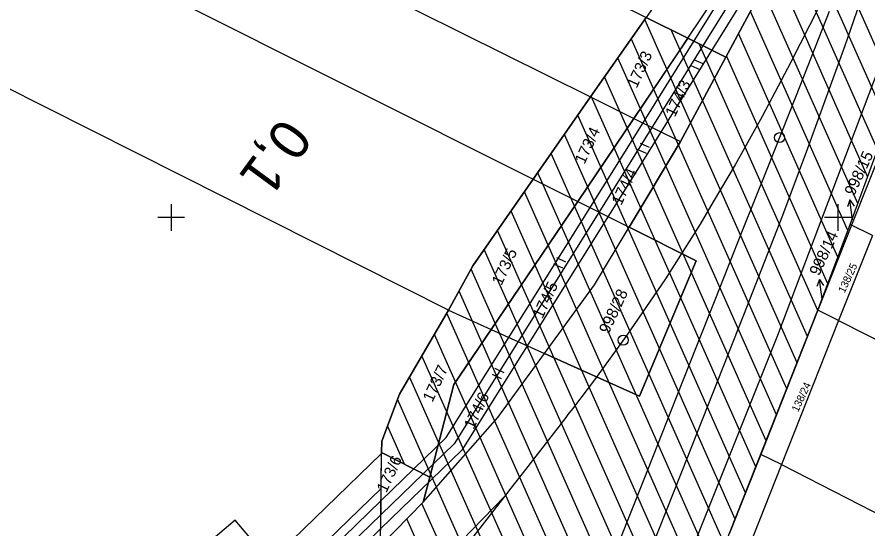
# Model space of a CAD drawing. Extents: x -755061 to -754557, y -1162352 to -1161657.
# Drawn here: x -754923.1 to -754795.5, y -1162146.7 to -1162070 of the extents above; entities that cross this region are included whole.
import ezdxf

# ---------------------------------------------------------------- set-up
doc = ezdxf.new("R2010")
doc.units = 0
for name, color, linetype in [('ADJ_Síť', 7, 'Continuous'), ('DTA-TZ', 7, 'Continuous'), ('DTA_DZ_DO_hranice', 7, 'Continuous'), ('DTA_DZ_DO_ostatní', 7, 'Continuous'), ('DTA_DZ_DO_ZPF', 7, 'Continuous'), ('DTA_ochranné pásmo', 7, 'Continuous'), ('DTA_projektovaný_stav', 7, 'Continuous'), ('DTA_správa_investora', 7, 'Continuous'), ('DTA_TZ_ZPF', 7, 'Continuous'), ('KN_Katastrální hranice', 7, 'Continuous'), ('KN_Vrstva 55', 7, 'Continuous'), ('KN_Vrstva 57', 7, 'Continuous'), ('KN_Vrstva 58', 7, 'Continuous'), ('Staniceni a namezniky', 7, 'Continuous'), ('Vrstva 1', 7, 'Continuous'), ('Vrstva 53', 7, 'Continuous')]:
    doc.layers.add(name, color=color, linetype=linetype)

msp = doc.modelspace()

# ---------------------------------------------------------------- linework, layer by layer
at = {"layer": 'ADJ_Síť'}
for points in [[(-754900, -1162098), (-754900, -1162100), (-754900, -1162102)], [(-754900, -1162098), (-754900, -1162100), (-754900, -1162102)], [(-754800, -1162098), (-754800, -1162100), (-754800, -1162102)], [(-754800, -1162098), (-754800, -1162100), (-754800, -1162102)], [(-754898, -1162100), (-754900, -1162100), (-754902, -1162100)], [(-754898, -1162100), (-754900, -1162100), (-754902, -1162100)], [(-754798, -1162100), (-754800, -1162100), (-754802, -1162100)], [(-754798, -1162100), (-754800, -1162100), (-754802, -1162100)]]:
    msp.add_lwpolyline(points, dxfattribs=at)
at = {"layer": 'DTA-TZ'}
msp.add_lwpolyline([(-754815.64, -1162062.89), (-754809.29, -1162051.78), (-754815.21, -1162048.8), (-754824.54, -1162063.98), (-754828.75, -1162070.02), (-754822.47, -1162073.13)], close=True, dxfattribs=at)
msp.add_lwpolyline([(-754923.5, -1162192.2), (-754927.24, -1162190.37), (-754917.66, -1162184.92), (-754903.67, -1162174.98), (-754894.6, -1162165.92), (-754868.47, -1162140.62), (-754868.42, -1162135.23), (-754861.18, -1162138.93), (-754862.16, -1162142.69), (-754868.56, -1162149.23), (-754896.07, -1162173.88), (-754915.78, -1162187.87), (-754923.5, -1162192.2)], dxfattribs=at)
at = {"layer": 'DTA_DZ_DO_hranice'}
for points in [[(-754816.76, -1162075.96), (-754812.88, -1162068.75), (-754805.89, -1162053.43), (-754794.46, -1162027.05), (-754775.38, -1161978.82), (-754774.5, -1161950.49), (-754763.88, -1161940.21)], [(-754785.9, -1161947.61), (-754784.8, -1161953.94), (-754785.77, -1161974.89), (-754795.69, -1162003.82), (-754808.6, -1162035.49), (-754813.58, -1162046.15), (-754815.21, -1162048.8), (-754824.54, -1162063.98), (-754828.75, -1162070.02), (-754837.06, -1162081.94), (-754845.66, -1162094.27), (-754854.71, -1162107.25), (-754858.37, -1162113.93), (-754865.75, -1162126.5), (-754868.4, -1162133.56), (-754868.42, -1162135.23)], [(-754882.86, -1162162.04), (-754868.56, -1162149.23), (-754862.16, -1162142.69), (-754850.97, -1162130.01), (-754843.96, -1162120.41), (-754829.74, -1162126.8), (-754821.22, -1162106.53), (-754831.28, -1162101.48), (-754823.58, -1162088.63), (-754816.76, -1162075.96)], [(-754868.42, -1162135.23), (-754868.42, -1162135.42), (-754885.14, -1162151.61), (-754890.41, -1162145.41), (-754900.32, -1162153.82), (-754894.5, -1162160.68), (-754900.94, -1162166.91), (-754920.36, -1162180.69), (-754945.08, -1162194.78)]]:
    msp.add_lwpolyline(points, dxfattribs=at)
at = {"layer": 'DTA_DZ_DO_ostatní'}
msp.add_lwpolyline([(-754822.47, -1162073.13), (-754830.58, -1162085.16), (-754839, -1162097.61), (-754851.98, -1162116.8), (-754857.56, -1162125.05), (-754861.18, -1162138.93), (-754868.42, -1162135.23), (-754868.4, -1162133.56), (-754865.75, -1162126.5), (-754858.37, -1162113.93), (-754854.71, -1162107.25), (-754845.66, -1162094.27), (-754837.06, -1162081.94), (-754828.75, -1162070.02), (-754822.47, -1162073.13)], dxfattribs=at)
msp.add_lwpolyline([(-754843.96, -1162120.41), (-754836.46, -1162110.13), (-754831.28, -1162101.48), (-754821.22, -1162106.53), (-754829.74, -1162126.8)], close=True, dxfattribs=at)
at = {"layer": 'DTA_DZ_DO_ZPF'}
msp.add_lwpolyline([(-754822.47, -1162073.13), (-754830.58, -1162085.16), (-754839, -1162097.61), (-754851.98, -1162116.8), (-754857.56, -1162125.05), (-754861.18, -1162138.93), (-754862.16, -1162142.69), (-754850.97, -1162130.01), (-754843.96, -1162120.41), (-754836.46, -1162110.13), (-754831.28, -1162101.48), (-754823.58, -1162088.63), (-754816.76, -1162075.96)], close=True, dxfattribs=at)
msp.add_lwpolyline([(-754927.24, -1162190.37), (-754917.66, -1162184.92), (-754903.67, -1162174.98), (-754894.6, -1162165.92), (-754868.47, -1162140.62), (-754868.42, -1162135.42), (-754885.14, -1162151.61), (-754890.41, -1162145.41), (-754900.32, -1162153.82), (-754894.5, -1162160.68), (-754900.94, -1162166.91), (-754920.36, -1162180.69), (-754932.68, -1162187.72)], dxfattribs=at)
at = {"layer": 'DTA_ochranné pásmo'}
for p, q in [((-754832.34, -1162090.86), (-754811.2, -1162056.88)), ((-754808.54, -1162058.27), (-754829.8, -1162092.44)), ((-754858.72, -1162132.98), (-754832.34, -1162090.86)), ((-754829.8, -1162092.44), (-754856.37, -1162134.88)), ((-754868.49, -1162142.45), (-754858.72, -1162132.98)), ((-754856.37, -1162134.88), (-754868.53, -1162146.66)), ((-754868.49, -1162142.45), (-754897.74, -1162170.77)), ((-754868.53, -1162146.66), (-754868.49, -1162142.45)), ((-754895.81, -1162173.08), (-754868.53, -1162146.66))]:
    msp.add_line(p, q, dxfattribs=at)
at = {"layer": 'DTA_projektovaný_stav'}
msp.add_lwpolyline([(-754758.34, -1161933.06), (-754762.34, -1161937.68), (-754763.29, -1161936.85), (-754776.47, -1161949.62), (-754777.37, -1161978.41), (-754796.3, -1162026.28), (-754809.87, -1162057.58), (-754831.07, -1162091.65), (-754857.54, -1162133.93), (-754885.68, -1162161.18), (-754896.77, -1162171.93), (-754916.86, -1162186.18), (-754942.05, -1162200.54), (-754965.03, -1162211.64), (-754990.89, -1162220.78), (-755014.11, -1162227.27), (-755008.76, -1162253.14), (-755005.05, -1162256.17)], dxfattribs=at)
at = {"layer": 'DTA_správa_investora'}
for p, q in [((-754791.04, -1162081.76), (-754810.13, -1162038.77)), ((-754792.53, -1162085.79), (-754806.69, -1162053.92)), ((-754794.02, -1162089.83), (-754808.28, -1162057.73)), ((-754795.51, -1162093.87), (-754809.87, -1162061.54)), ((-754796.99, -1162097.92), (-754811.46, -1162065.35)), ((-754798.48, -1162101.96), (-754813.07, -1162069.11)), ((-754806.09, -1162121.79), (-754828.95, -1162070.31)), ((-754804.54, -1162117.88), (-754824.97, -1162071.89)), ((-754807.63, -1162125.69), (-754830.96, -1162073.19)), ((-754799.98, -1162105.96), (-754814.87, -1162072.45)), ((-754802.99, -1162113.98), (-754820.76, -1162073.98)), ((-754809.18, -1162129.6), (-754832.96, -1162076.06)), ((-754801.49, -1162109.97), (-754816.67, -1162075.79)), ((-754810.73, -1162133.5), (-754834.97, -1162078.94)), ((-754812.28, -1162137.41), (-754836.97, -1162081.82)), ((-754813.83, -1162141.31), (-754838.98, -1162084.69)), ((-754815.37, -1162145.22), (-754840.98, -1162087.57)), ((-754816.94, -1162149.08), (-754842.99, -1162090.44)), ((-754818.53, -1162152.9), (-754844.99, -1162093.32)), ((-754820.12, -1162156.71), (-754847, -1162096.19)), ((-754821.71, -1162160.53), (-754849, -1162099.07)), ((-754823.29, -1162164.34), (-754851.01, -1162101.94)), ((-754824.88, -1162168.15), (-754853.02, -1162104.82)), ((-754826.47, -1162171.97), (-754854.99, -1162107.76)), ((-754828.06, -1162175.78), (-754856.8, -1162111.07)), ((-754829.65, -1162179.6), (-754858.62, -1162114.36)), ((-754831.24, -1162183.41), (-754860.49, -1162117.55)), ((-754832.82, -1162187.23), (-754862.36, -1162120.73)), ((-754834.41, -1162191.04), (-754864.23, -1162123.91)), ((-754836, -1162194.86), (-754866.03, -1162127.25)), ((-754864.99, -1162136.98), (-754867.53, -1162131.25)), ((-754837.59, -1162198.67), (-754862.36, -1162142.9)), ((-754839.18, -1162202.48), (-754864.62, -1162145.2))]:
    msp.add_line(p, q, dxfattribs=at)
for points in [[(-755057.07, -1162235.3), (-755060.75, -1162244.84), (-754884.82, -1162312.55), (-754851.45, -1162231.96), (-754816.22, -1162147.35), (-754802.96, -1162113.9), (-754798.15, -1162101.07), (-754793.13, -1162087.4), (-754789, -1162076.26), (-754760.29, -1162004.33), (-754756.33, -1161996.85), (-754754.27, -1161988.55), (-754747.84, -1161978.77), (-754745.89, -1161978.47), (-754750.32, -1161972.64), (-754749.74, -1161970.12), (-754747.41, -1161959.83), (-754731.42, -1161979.09), (-754717.5, -1161955.11), (-754704.12, -1161932.06), (-754747.69, -1161915.3)], [(-754812.88, -1162068.75), (-754816.76, -1162075.96), (-754822.47, -1162073.13), (-754828.75, -1162070.02), (-754837.06, -1162081.94), (-754854.71, -1162107.25), (-754858.37, -1162113.93), (-754865.75, -1162126.5), (-754868.4, -1162133.56), (-754868.42, -1162135.23), (-754861.18, -1162138.93), (-754862.16, -1162142.69), (-754868.56, -1162149.23), (-754896.07, -1162173.88), (-754900.06, -1162176.77), (-754915.78, -1162187.87), (-754923.5, -1162192.2)]]:
    msp.add_lwpolyline(points, dxfattribs=at)
at = {"layer": 'DTA_TZ_ZPF'}
msp.add_lwpolyline([(-754822.47, -1162073.13), (-754815.64, -1162062.89), (-754810.12, -1162053.37), (-754809.29, -1162051.78), (-754806.4, -1162053.23), (-754812.88, -1162068.75), (-754816.76, -1162075.96)], close=True, dxfattribs=at)
at = {"layer": 'KN_Katastrální hranice'}
for p, q in [((-754792.54, -1162087.63), (-754797.91, -1162101.16)), ((-754797.91, -1162101.16), (-754802.96, -1162113.9)), ((-754802.96, -1162113.9), (-754811.54, -1162135.54)), ((-754811.54, -1162135.54), (-754816.22, -1162147.35))]:
    msp.add_line(p, q, dxfattribs=at)
at = {"layer": 'KN_Vrstva 55'}
for p, q in [((-754828.75, -1162070.02), (-754837.06, -1162081.94)), ((-754828.75, -1162070.02), (-754822.47, -1162073.13)), ((-754822.47, -1162073.13), (-754816.76, -1162075.96)), ((-754816.76, -1162075.96), (-754823.58, -1162088.63)), ((-754837.06, -1162081.94), (-754845.66, -1162094.27)), ((-754837.06, -1162081.94), (-754830.58, -1162085.16)), ((-754839, -1162097.61), (-754830.58, -1162085.16)), ((-754830.58, -1162085.16), (-754823.58, -1162088.63)), ((-754798.15, -1162101.07), (-754793.13, -1162087.4)), ((-754792.54, -1162087.63), (-754797.91, -1162101.16)), ((-754792.54, -1162087.63), (-754797.91, -1162101.16)), ((-754823.58, -1162088.63), (-754831.28, -1162101.48)), ((-754845.66, -1162094.27), (-754839, -1162097.61)), ((-754851.98, -1162116.8), (-754839, -1162097.61)), ((-754839, -1162097.61), (-754831.28, -1162101.48)), ((-754802.96, -1162113.9), (-754798.15, -1162101.07)), ((-754797.91, -1162101.16), (-754802.96, -1162113.9)), ((-754797.91, -1162101.16), (-754802.96, -1162113.9)), ((-754797.91, -1162101.16), (-754798.15, -1162101.07)), ((-754794.8, -1162102.72), (-754797.91, -1162101.16)), ((-754794.8, -1162102.72), (-754799.86, -1162115.47)), ((-754802.96, -1162113.9), (-754811.54, -1162135.54)), ((-754802.96, -1162113.9), (-754811.54, -1162135.54)), ((-754799.86, -1162115.47), (-754802.96, -1162113.9)), ((-754799.86, -1162115.47), (-754808.43, -1162137.05)), ((-754851.98, -1162116.8), (-754843.96, -1162120.41)), ((-754868.56, -1162149.23), (-754868.42, -1162135.23)), ((-754861.18, -1162138.93), (-754868.42, -1162135.23)), ((-754811.54, -1162135.54), (-754816.22, -1162147.35)), ((-754811.54, -1162135.54), (-754816.22, -1162147.35)), ((-754808.43, -1162137.05), (-754811.54, -1162135.54)), ((-754808.43, -1162137.05), (-754817.91, -1162160.94)), ((-754862.16, -1162142.69), (-754861.18, -1162138.93)), ((-754868.56, -1162149.23), (-754862.16, -1162142.69))]:
    msp.add_line(p, q, dxfattribs=at)
for points in [[(-754888.68, -1162311.07), (-754870.17, -1162267.96), (-754836.4, -1162183.6), (-754824.89, -1162157.4), (-754808.97, -1162117.64), (-754790.52, -1162068.93), (-754761.32, -1161999.17), (-754754.27, -1161988.55)], [(-754966.42, -1161999.75), (-754920.4, -1162024.65), (-754828.75, -1162070.02)], [(-754971.75, -1162013.61), (-754934.11, -1162033.82), (-754837.06, -1162081.94)], [(-754977.09, -1162027.47), (-754900.68, -1162066.68), (-754845.66, -1162094.27)], [(-754815.21, -1162048.8), (-754824.54, -1162063.98), (-754828.75, -1162070.02)], [(-754858.37, -1162113.93), (-754985.69, -1162049.81)], [(-754822.47, -1162073.13), (-754815.64, -1162062.89), (-754810.12, -1162053.37), (-754809.29, -1162051.78)], [(-754806.4, -1162053.23), (-754812.88, -1162068.75), (-754816.76, -1162075.96)], [(-754830.58, -1162085.16), (-754823.72, -1162075.01), (-754822.47, -1162073.13)], [(-754845.66, -1162094.27), (-754854.71, -1162107.25), (-754858.37, -1162113.93)], [(-754843.96, -1162120.41), (-754836.46, -1162110.13), (-754831.28, -1162101.48)], [(-754831.28, -1162101.48), (-754821.22, -1162106.53), (-754829.74, -1162126.8), (-754843.96, -1162120.41)], [(-754868.42, -1162135.23), (-754868.4, -1162133.56), (-754865.75, -1162126.5), (-754858.37, -1162113.93)], [(-754865.75, -1162126.5), (-754858.37, -1162113.93), (-754851.98, -1162116.8)], [(-754799.86, -1162115.47), (-754745.23, -1162143.07), (-754710.27, -1162161.07)], [(-754861.18, -1162138.93), (-754857.56, -1162125.05), (-754851.98, -1162116.8)], [(-754862.16, -1162142.69), (-754850.97, -1162130.01), (-754843.96, -1162120.41)], [(-754808.43, -1162137.05), (-754718.71, -1162183.01)]]:
    msp.add_lwpolyline(points, dxfattribs=at)
at = {"layer": 'KN_Vrstva 57'}
for p, q in [((-754798.16, -1162097.38), (-754798.52, -1162098.44)), ((-754797.77, -1162100.36), (-754798.16, -1162097.38)), ((-754798.16, -1162097.38), (-754797.53, -1162098.31)), ((-754802.74, -1162109.29), (-754803.11, -1162110.34)), ((-754802.35, -1162112.26), (-754802.74, -1162109.29)), ((-754802.74, -1162109.29), (-754802.11, -1162110.22))]:
    msp.add_line(p, q, dxfattribs=at)
at = {"layer": 'KN_Vrstva 58'}
for p, q in [((-754820.63, -1162077.9), (-754821.99, -1162077.27)), ((-754820.2, -1162077), (-754821.56, -1162076.36)), ((-754828.24, -1162089.53), (-754829.6, -1162088.9)), ((-754828.66, -1162090.44), (-754830.02, -1162089.8)), ((-754840.78, -1162106.72), (-754842.14, -1162106.08)), ((-754841.21, -1162107.62), (-754842.57, -1162106.99)), ((-754850.01, -1162123.29), (-754851.37, -1162122.66)), ((-754850.43, -1162124.2), (-754851.79, -1162123.57))]:
    msp.add_line(p, q, dxfattribs=at)
at = {"layer": 'Staniceni a namezniky'}
for centre in [(-754808.73, -1162088.04), (-754832.17, -1162118.4)]:
    msp.add_circle(centre, 0.75, dxfattribs=at)
at = {"layer": 'Vrstva 1'}
for points in [[(-754814.09, -1162114.62), (-754808.25, -1162099.68), (-754804.47, -1162089.62), (-754798.9, -1162074.23), (-754793.63, -1162059.03), (-754788.99, -1162045.27)], [(-754802.82, -1162068.46), (-754807.01, -1162076.73), (-754811.35, -1162084.87), (-754815.39, -1162092.12), (-754818.66, -1162097.67), (-754820.65, -1162100.99), (-754825.85, -1162109.19), (-754831.64, -1162117.68), (-754836.49, -1162124.37), (-754839.8, -1162128.71), (-754840.46, -1162129.57), (-754840.79, -1162129.99), (-754847.19, -1162138.25), (-754849.01, -1162140.58), (-754849.98, -1162141.84), (-754854.92, -1162148.19), (-754860.18, -1162155.01)], [(-754855.13, -1162205.06), (-754851.41, -1162195.67), (-754847.87, -1162186.72), (-754844.23, -1162177.57), (-754840.47, -1162168.07), (-754836.48, -1162158.01), (-754832.72, -1162148.55), (-754829.03, -1162139.24), (-754824.91, -1162128.83), (-754821.22, -1162119.52), (-754818.37, -1162112.34), (-754814.26, -1162101.97), (-754810.6, -1162092.76), (-754806.3, -1162081.9), (-754802.77, -1162073.01), (-754801.21, -1162069.06)], [(-754832.58, -1162161.33), (-754823.38, -1162138.13), (-754814.09, -1162114.62)], [(-754839.8, -1162128.71), (-754840.46, -1162129.57), (-754840.79, -1162129.99), (-754847.19, -1162138.25), (-754849.01, -1162140.58), (-754849.98, -1162141.84), (-754861.22, -1162153.45), (-754861.54, -1162153.77), (-754867.4, -1162159.65), (-754873.88, -1162165.79), (-754880.89, -1162172.03), (-754888.58, -1162178.44), (-754889.11, -1162178.86), (-754895.68, -1162183.99), (-754902.86, -1162189.27), (-754906.67, -1162191.94), (-754914.99, -1162197.47), (-754922.58, -1162202.18), (-754930.39, -1162206.7)]]:
    msp.add_lwpolyline(points, dxfattribs=at)
at = {"layer": 'Vrstva 53'}
for points in [[(-754884.82, -1162312.55), (-754851.45, -1162231.96), (-754816.22, -1162147.35), (-754802.96, -1162113.9), (-754798.15, -1162101.07), (-754793.13, -1162087.4), (-754789, -1162076.26), (-754760.29, -1162004.33), (-754756.33, -1161996.85), (-754754.27, -1161988.55), (-754747.84, -1161978.77), (-754745.89, -1161978.47), (-754750.32, -1161972.64), (-754749.74, -1161970.12), (-754747.41, -1161959.83), (-754731.42, -1161979.09), (-754717.5, -1161955.11), (-754704.12, -1161932.06)], [(-754812.88, -1162068.75), (-754816.76, -1162075.96), (-754822.47, -1162073.13), (-754828.75, -1162070.02), (-754837.06, -1162081.94), (-754854.71, -1162107.25), (-754858.37, -1162113.93), (-754865.75, -1162126.5), (-754868.4, -1162133.56), (-754868.42, -1162135.23), (-754861.18, -1162138.93), (-754862.16, -1162142.69), (-754868.56, -1162149.23), (-754896.07, -1162173.88), (-754900.06, -1162176.77), (-754915.78, -1162187.87), (-754923.5, -1162192.2)]]:
    msp.add_lwpolyline(points, dxfattribs=at)

# ---------------------------------------------------------------- texts
at = {"layer": 'KN_Vrstva 57'}
for s, height, p in [('173/3', 1.7, (-754830.16, -1162080.73)), ('174/3', 1.7, (-754824.42, -1162085.06)), ('173/4', 1.7, (-754837.99, -1162092.13)), ('998/15', 1.7, (-754797.54, -1162096.87)), ('174/4', 1.7, (-754832.47, -1162098.3)), ('998/14', 1.7, (-754802.81, -1162108.87)), ('173/5', 1.7, (-754850.44, -1162110.31)), ('138/25', 1.139, (-754798.97, -1162111.43)), ('174/5', 1.7, (-754844.3, -1162115.3)), ('998/28', 1.7, (-754834.36, -1162117.56)), ('173/7', 1.7, (-754860.8, -1162127.81)), ('138/24', 1.139, (-754805.94, -1162129.27)), ('174/6', 1.7, (-754854.62, -1162131.89)), ('173/6', 1.7, (-754867.71, -1162141.39))]:
    msp.add_text(s, height=height, rotation=65, dxfattribs=at).set_placement(p)
at = {"layer": 'Staniceni a namezniky'}
msp.add_text('0,1', height=6, rotation=233.7782, dxfattribs=at).set_placement((-754883.38, -1162084.78))

doc.saveas('drawing.dxf')
